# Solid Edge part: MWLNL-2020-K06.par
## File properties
Author: LABUSIG
Template: iso metric part.par
Last saved by: LABUSIG
Revision: 1
Application: Solid Edge
Accuracy: 0.990
Username: LABUSIG
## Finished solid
Body 1: solid body, 285 faces, 726 edges, 443 vertices.
  Faces by surface: cylinder 112, spline 99, plane 71, cone 2, sphere 1
  Edges by curve: curve on surface 526, spline 134, line 62, circle 4
Body 2: solid body, 106 faces, 300 edges, 195 vertices.
  Faces by surface: plane 52, cylinder 22, torus 18, cone 7, spline 7
  Edges by curve: line 147, spline 56, curve on surface 52, circle 45
Bounding box of the edges (mm; curved faces can reach further): 25.037 x 27.000 x 125.037, from (0, 0, -125.0374) to (25.0369, 27, 0).
Cylindrical faces by radius (mm): R0.0163 x1, R0.0164 x1, R0.017 x1, R0.0173 x1, R0.0174 x1, R0.018 x1, R0.0182 x1, R0.0183 x1, R0.0184 x1, R0.0195 x1, R0.0198 x1, R0.0201 x1, R0.4 x2, R0.4008 x1, R0.7 x3, R0.8 x4, R1 x2, R1.0607 x3, R1.214 x3, R1.4996 x2, R1.5 x7, R1.5004 x1, R2 x1, R2.0882 x2, R2.0884 x1, R2.168 x3, R2.2001 x2, R2.45 x2, R2.5309 x3, R3.541 x1, R3.5411 x2, R3.7936 x3, R4 x2, R4.3249 x3, R5.1849 x3, R5.4407 x3, R6.5 x1, R7.3657 x3, R7.6687 x2, R7.6692 x1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
Conical faces (half-angle, radius in mm at the cone's reference point): 15 deg R15.2045 x3, 60.5 deg R2.653 x2, 75 deg R2.5 x2, 84.3068 deg R1.6998 x1, 84.3068 deg R1.6999 x1
Toroidal faces (ring radius, tube radius in mm): R3.4988 r1.5 x1, R12.5482 r5 x5, R19.2427 r3 x3, R24.0482 r6.5 x9
Spherical faces by radius (mm): R3.3777 x1
Planar faces by outward normal: +x 1, +y 2, +z 1, -x 1, -y 1, oblique 117
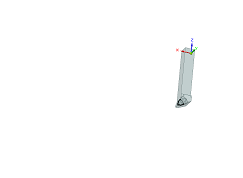
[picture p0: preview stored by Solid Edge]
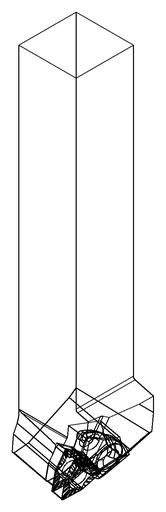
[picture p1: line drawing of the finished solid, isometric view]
